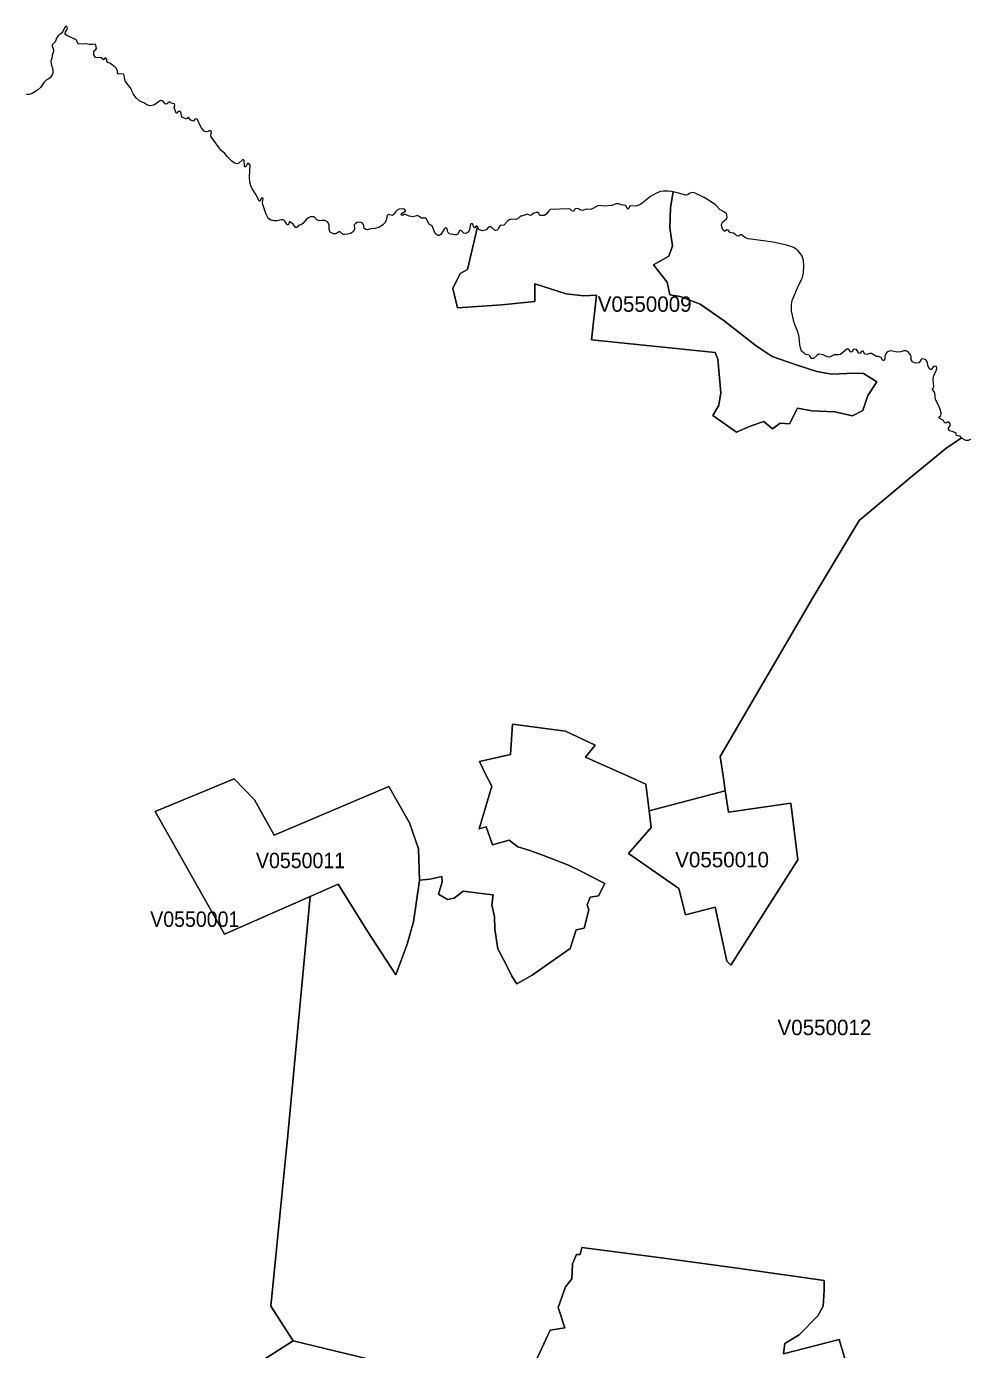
# Model space of a CAD drawing. Extents: x 369010 to 735936, y 6377141 to 6616555.
# Drawn here: x 434376 to 440462, y 6490450 to 6499050 of the extents above; entities that cross this region are included whole.
import ezdxf
from ezdxf.enums import TextEntityAlignment as Align

# ---------------------------------------------------------------- set-up
doc = ezdxf.new("R2010")
doc.units = 0
doc.header["$LTSCALE"] = 40
doc.layers.add('3', color=7, linetype='Continuous', lineweight=13)
doc.layers.add('4', color=7, linetype='Continuous')

msp = doc.modelspace()

# ---------------------------------------------------------------- linework, layer by layer
at = {"layer": '3'}
for points in [[(435015.02, 6498705), (435011.21, 6498730.82), (435006.25, 6498739.42), (434985.06, 6498742.4), (434977.62, 6498739.09), (434968.51, 6498743.39), (434967.69, 6498759.12), (434960.9, 6498776.83), (434951.47, 6498786.92), (434918.37, 6498811.09), (434906.12, 6498816.88), (434900, 6498823.66), (434898.01, 6498834.92), (434892.55, 6498844.85), (434887.09, 6498846.17), (434881.62, 6498836.57), (434877.32, 6498833.26), (434858.95, 6498849.48), (434839.59, 6498847.17), (434825.52, 6498848.82), (434820.06, 6498853.95), (434815.42, 6498866.86), (434814.43, 6498885.23), (434820.22, 6498896.82), (434826.68, 6498900.62), (434832.3, 6498907.41), (434827.67, 6498928.43), (434822.21, 6498936.04), (434804.83, 6498932.23), (434785.47, 6498931.9), (434759.65, 6498938.03), (434714.63, 6498936.04), (434701.06, 6498958.72), (434691.96, 6498966.66), (434638.17, 6498990.99), (434627.91, 6499000.92), (434631.05, 6499016.31), (434639.16, 6499029.22), (434643.63, 6499042.13), (434639.82, 6499050.24), (434631.05, 6499048.92), (434624.6, 6499041.8), (434612.35, 6499018.3), (434604.57, 6499007.7), (434582.39, 6498990.33), (434574.95, 6498978.41), (434563.03, 6498950.94), (434544, 6498930.91), (434543.33, 6498923.63), (434552.44, 6498897.81), (434552.11, 6498890.69), (434542.67, 6498864.21), (434540.52, 6498844.85), (434534.73, 6498825.48), (434536.88, 6498806.29), (434547.31, 6498767.56), (434547.31, 6498748.19), (434544.66, 6498735.29), (434530.43, 6498716.09), (434517.85, 6498707.15), (434505.1, 6498701.36), (434488.72, 6498686.3), (434468.53, 6498653.69), (434448.83, 6498635.65), (434412.92, 6498615.46), (434393.39, 6498608.18), (434375.68, 6498608.18)], [(436210.95, 6497807.3), (436199.7, 6497799.19), (436174.21, 6497769.24), (436162.63, 6497761.79), (436146.74, 6497757.65), (436133.83, 6497742.76), (436125.55, 6497742.76), (436109.66, 6497764.27), (436088.48, 6497780.16), (436084.34, 6497779.5), (436080.04, 6497761.79), (436074.25, 6497760.8), (436068.45, 6497765.27), (436057.2, 6497784.3), (436047.27, 6497792.41), (436031.71, 6497793.4), (436005.23, 6497786.95), (435984.71, 6497787.61), (435963.36, 6497793.4), (435953.1, 6497799.53), (435945.32, 6497808.79), (435932.74, 6497834.61), (435912.38, 6497892.7), (435911.23, 6497906.77), (435914.7, 6497933.25), (435908.91, 6497935.57), (435905.43, 6497934.58), (435894.34, 6497915.21), (435889.54, 6497915.54), (435869.52, 6497955.26), (435843.2, 6497993.83), (435834.1, 6498013.19), (435828.64, 6498039.01), (435825.99, 6498071.95), (435829.96, 6498147.58), (435822.85, 6498160.16), (435814.07, 6498158.67), (435803.15, 6498138.64), (435798.02, 6498137.32), (435792.89, 6498143.44), (435790.9, 6498179.85), (435787.43, 6498183.49), (435780.64, 6498183.99), (435757.47, 6498162.48), (435747.05, 6498156.68), (435729.01, 6498161.81), (435710.97, 6498175.05), (435682, 6498204.02), (435666.11, 6498223.71), (435640.96, 6498245.89), (435576.91, 6498333.61), (435575.25, 6498350.32), (435578.73, 6498359.76), (435576.58, 6498372), (435563.67, 6498372), (435554.9, 6498366.87), (435544.96, 6498365.22), (435531.39, 6498370.02), (435513.68, 6498391.04), (435498.29, 6498419.34), (435488.2, 6498446.15), (435484.39, 6498449.29), (435471.81, 6498448.47), (435463.04, 6498434.23), (435444.01, 6498441.02), (435429.94, 6498459.39), (435425.97, 6498459.39), (435419.18, 6498450.29), (435415.38, 6498449.96), (435391.54, 6498458.73), (435383.43, 6498467.67), (435382.44, 6498485.21), (435378.3, 6498494.48), (435371.19, 6498499.94), (435362.25, 6498496.79), (435353.15, 6498486.04), (435348.68, 6498486.04), (435337.42, 6498522.61), (435340.24, 6498538.67), (435338.25, 6498546.78), (435318.06, 6498550.91), (435310.28, 6498559.02), (435305.81, 6498560.18), (435296.05, 6498551.24), (435285.12, 6498546.11), (435278.67, 6498548.27), (435267.08, 6498560.84), (435259.31, 6498565.81), (435248.05, 6498567.96), (435203.86, 6498539), (435180.03, 6498534.2), (435158.84, 6498540.65), (435140.14, 6498554.39), (435114.32, 6498565.15), (435090.16, 6498586.33), (435069.47, 6498612.15), (435063.02, 6498624.4), (435057.89, 6498645.09), (435021.14, 6498692.09), (435015.02, 6498705)], [(437307.91, 6497746.73), (437244.36, 6497469.68), (437195.87, 6497444.52), (437148.7, 6497347.53), (437178.65, 6497220.43), (437465.8, 6497241.12), (437682.12, 6497261.64), (437681.46, 6497377.32), (437886.02, 6497311.95), (437999.72, 6497298.55), (438081.98, 6497304.17), (438049.87, 6497012.89), (438852.89, 6496929.8), (438870.93, 6496887.76), (438890.13, 6496669.13), (438877.72, 6496589.03), (438837.5, 6496520.35), (438992.91, 6496413.26), (439080.79, 6496452.16), (439169.67, 6496481.45), (439226.6, 6496434.95), (439276.75, 6496472.18), (439336.17, 6496467.05), (439388.13, 6496569.83), (439481.31, 6496552.29), (439631.76, 6496544.34), (439746.78, 6496519.35), (439812.82, 6496554.27), (439846.58, 6496652.42), (439904.84, 6496740.3), (439818.61, 6496794.25), (439759.69, 6496796.74), (439609.91, 6496790.12), (439515.57, 6496806.34), (439386.15, 6496847.71), (439224.95, 6496904.81), (439119.52, 6496973.99), (438912.31, 6497137.18), (438755.91, 6497244.59), (438626.48, 6497295.23), (438558.63, 6497306.16), (438542.41, 6497388.25), (438453.04, 6497499.8), (438551.84, 6497556.57), (438577, 6497624.92), (438558.3, 6497741.93), (438562.93, 6497872.51), (438580.64, 6497974.3), (438580.64, 6497974.63), (438569.39, 6497977.11), (438546.05, 6497980.09), (438517.09, 6497980.59), (438496.4, 6497976.45), (438463.63, 6497962.55), (438433.84, 6497945.17), (438367.47, 6497892.04), (438338.51, 6497881.45), (438301.43, 6497884.59), (438297.13, 6497880.95), (438292.99, 6497868.04), (438286.04, 6497862.75), (438281.57, 6497865.89), (438272.31, 6497886.42), (438242.51, 6497891.38), (438226.3, 6497898.17), (438210.9, 6497897.84), (438179.95, 6497885.92), (438133.45, 6497882.94), (438094.72, 6497885.59), (438046.39, 6497860.1), (438015.44, 6497863.58), (437990.29, 6497854.64), (437979.36, 6497856.62), (437960, 6497865.89), (437945.93, 6497865.56), (437940.8, 6497863.08), (437931.7, 6497847.85), (437922.26, 6497851.66), (437911.01, 6497863.24), (437900.75, 6497865.23), (437780.76, 6497859.44), (437771.49, 6497851), (437755.6, 6497829.81), (437743.35, 6497821.37), (437716.71, 6497821.37), (437711.58, 6497825.68), (437707.61, 6497835.61), (437700.82, 6497841.07), (437689.9, 6497841.73), (437674.84, 6497837.26), (437654.48, 6497821.7), (437646.04, 6497822.7), (437634.45, 6497830.14), (437594.57, 6497817.23), (437587.45, 6497817.57), (437572.55, 6497802.67), (437558.32, 6497795.88), (437532.67, 6497796.55), (437517.11, 6497793.4), (437503.54, 6497784.63)], [(439435.8, 6496922.69), (439415.44, 6496939.07), (439408.32, 6496960.42), (439404.52, 6496981.6), (439400.71, 6497031.26), (439392.6, 6497059.72), (439367.11, 6497123.44), (439350.4, 6497201.56), (439350.4, 6497242.11), (439353.21, 6497267.93), (439389.13, 6497351.67), (439415.44, 6497405.3), (439420.57, 6497419.36), (439427.03, 6497448.49), (439430.01, 6497493.51), (439427.36, 6497528.43), (439418.42, 6497557.39), (439410.97, 6497570.63), (439392.27, 6497592.48), (439370.76, 6497609.86), (439359, 6497616.15), (439318.46, 6497628.39), (439231.4, 6497647.1), (439167.68, 6497657.69), (439069.04, 6497669.61), (439045.71, 6497678.54), (439031.64, 6497691.45), (439023.86, 6497695.09), (439018.73, 6497695.09), (439004.5, 6497687.98), (438994.23, 6497689.3), (438972.22, 6497707.34), (438956.83, 6497708.66), (438950.71, 6497711.48), (438939.12, 6497727.03), (438930.35, 6497727.86), (438919.43, 6497719.92), (438914.3, 6497719.59), (438904.2, 6497728.52), (438896.42, 6497748.22), (438895.59, 6497759.8), (438900.39, 6497778.18), (438927.37, 6497799.19), (438931.34, 6497808.79), (438930.35, 6497826.17), (438924.89, 6497835.27), (438914.3, 6497844.05), (438886.16, 6497858.45), (438855.21, 6497889.73), (438821.78, 6497915.21), (438782.72, 6497938.38), (438724.63, 6497965.53), (438707.25, 6497970.33), (438692.19, 6497967.18), (438673.82, 6497956.09), (438662.07, 6497954.27), (438615.73, 6497967.18), (438580.64, 6497974.63), (438580.64, 6497974.3), (438562.93, 6497872.51), (438558.3, 6497741.93), (438577, 6497624.92), (438551.84, 6497556.57), (438453.04, 6497499.8), (438542.41, 6497388.25), (438558.63, 6497306.16), (438626.48, 6497295.23), (438755.91, 6497244.59), (438912.31, 6497137.18), (439119.52, 6496973.99), (439224.95, 6496904.81), (439386.15, 6496847.71), (439515.57, 6496806.34), (439609.91, 6496790.12), (439759.69, 6496796.74), (439818.61, 6496794.25), (439904.84, 6496740.3), (439846.58, 6496652.42), (439812.82, 6496554.27), (439746.78, 6496519.35), (439631.76, 6496544.34), (439481.31, 6496552.29), (439388.13, 6496569.83), (439336.17, 6496467.05), (439276.75, 6496472.18), (439226.6, 6496434.95), (439169.67, 6496481.45), (439080.79, 6496452.16), (438992.91, 6496413.26), (438837.5, 6496520.35), (438877.72, 6496589.03), (438890.13, 6496669.13), (438870.93, 6496887.76), (438852.89, 6496929.8), (438049.87, 6497012.89), (438081.98, 6497304.17), (437999.72, 6497298.55), (437886.02, 6497311.95), (437681.46, 6497377.32), (437682.12, 6497261.64)], [(437682.12, 6497261.64), (437465.8, 6497241.12), (437178.65, 6497220.43), (437148.7, 6497347.53), (437195.87, 6497444.52), (437244.36, 6497469.68), (437307.91, 6497746.73), (437305.27, 6497751.2), (437299.64, 6497753.18), (437291.36, 6497741.27), (437288.05, 6497741.93), (437276.96, 6497768.25), (437264.39, 6497766.59), (437260.58, 6497756.66), (437256.61, 6497728.19), (437248.66, 6497713.13), (437232.44, 6497705.35), (437220.53, 6497707.34), (437205.14, 6497722.07), (437196.03, 6497725.38), (437189.25, 6497720.25), (437181.63, 6497699.89), (437174.19, 6497695.42), (437159.95, 6497695.75), (437127.35, 6497702.71), (437114.77, 6497712.8), (437111.96, 6497735.64), (437105.5, 6497741.1), (437101.36, 6497741.1), (437092.59, 6497732.17), (437069.42, 6497696.91), (437059.66, 6497690.46), (437049.73, 6497691.78), (437036.82, 6497699.89), (437026.23, 6497718.59), (437016.79, 6497750.54), (437011, 6497756.33), (436998.09, 6497761.46), (436991.64, 6497767.58), (436977.9, 6497799.19), (436971.11, 6497803.33), (436944.63, 6497803.99), (436918.15, 6497821.7), (436890.51, 6497811.77), (436864.69, 6497816.9), (436840.53, 6497828.49), (436831.1, 6497828.49), (436821.5, 6497822.03), (436811.9, 6497825.01), (436813.72, 6497834.61), (436839.54, 6497850.17), (436840.86, 6497854.31), (436835.07, 6497863.24), (436821.5, 6497864.9), (436800.15, 6497862.09), (436787.24, 6497855.96), (436774.49, 6497844.38), (436763.41, 6497827.5), (436755.46, 6497821.37), (436728.32, 6497827.5), (436720.87, 6497820.38), (436714.42, 6497789.43), (436706.47, 6497773.38), (436693.56, 6497759.8), (436671.88, 6497745.9), (436643.58, 6497737.63), (436615.11, 6497735.64), (436590.95, 6497728.86), (436583.67, 6497729.85), (436571.75, 6497736.3), (436569.43, 6497755.01), (436565.79, 6497765.6), (436558.18, 6497773.04), (436540.97, 6497777.51), (436526.9, 6497775.03), (436515.31, 6497768.91), (436506.54, 6497759.8), (436508.53, 6497732.5), (436502.74, 6497716.61), (436483.7, 6497705.35), (436464.34, 6497699.89), (436444.98, 6497697.58), (436435.71, 6497698.57), (436416.01, 6497714.79), (436408.56, 6497715.95), (436386.88, 6497702.54), (436371.49, 6497703.04), (436351.13, 6497713.13), (436347.66, 6497717.27), (436344.35, 6497732.83), (436345.34, 6497758.48), (436340.21, 6497771.39), (436333.43, 6497780.16), (436317.37, 6497788.27), (436298.01, 6497788.6), (436278.64, 6497785.95), (436263.42, 6497793.73), (436246.04, 6497812.43), (436223.86, 6497811.77), (436210.95, 6497807.3)], [(437503.54, 6497784.63), (437479.71, 6497758.81), (437456.54, 6497755.34), (437450.41, 6497748.22), (437443.63, 6497732.17), (437436.51, 6497726.7), (437424.59, 6497724.06), (437419.79, 6497726.04), (437398.11, 6497747.23), (437385.87, 6497747.23), (437380.74, 6497745.07), (437365.01, 6497729.19), (437349.46, 6497723.06), (437341.18, 6497722.73), (437320.82, 6497727.86), (437317.02, 6497730.84), (437307.91, 6497746.73)], [(440412.6, 6496410.78), (440394.56, 6496418.23), (440379.67, 6496421.04), (440373.88, 6496425.01), (440370.07, 6496432.46), (440369.74, 6496440.08), (440381.65, 6496455.63), (440382.32, 6496468.21), (440372.55, 6496477.15), (440362.29, 6496477.15), (440358.32, 6496474.67), (440347.73, 6496473.01), (440344.25, 6496475.49), (440337.46, 6496488.4), (440313.63, 6496502.31), (440310.65, 6496507.1), (440310.65, 6496512.9), (440320.09, 6496522.33), (440323.23, 6496529.12), (440323.23, 6496538.05), (440317.44, 6496559.4), (440305.52, 6496589.36), (440285.83, 6496625.77), (440282.68, 6496669.3), (440265.8, 6496689.66), (440266.13, 6496693.79), (440272.92, 6496702.23), (440275.23, 6496710.84), (440270.77, 6496753.37), (440272.92, 6496774.72), (440291.95, 6496817.26), (440294.27, 6496828.84), (440291.62, 6496839.27), (440288.48, 6496841.42), (440273.91, 6496839.44), (440258.85, 6496820.24), (440253.88, 6496819.91), (440246.27, 6496824.05), (440239.15, 6496840.43), (440231.38, 6496871.38), (440221.45, 6496885.61), (440210.69, 6496888.59), (440197.78, 6496888.76), (440192.32, 6496885.94), (440185.86, 6496873.7), (440177.26, 6496863.1), (440156.9, 6496862.11), (440136.54, 6496870.22), (440127.27, 6496882.14), (440128.27, 6496905.64), (440125.62, 6496912.76), (440111.39, 6496931.46), (440100.46, 6496940.39), (440092.85, 6496942.38), (440079.94, 6496941.72), (440060.58, 6496935.93), (440034.1, 6496933.94), (439998.68, 6496940.73), (439985.77, 6496940.06), (439969.88, 6496932.28), (439968.72, 6496929.14), (439964.75, 6496927.49), (439957.63, 6496906.3), (439956.81, 6496890.74), (439951.51, 6496879.82), (439944.23, 6496879.16), (439931.98, 6496898.19), (439915.43, 6496904.31), (439902.52, 6496905.64), (439870.58, 6496923.35), (439859.99, 6496924.67), (439839.96, 6496918.88), (439827.22, 6496920.7), (439815.3, 6496938.74), (439810.67, 6496939.07), (439805.2, 6496936.59), (439794.28, 6496925), (439787.16, 6496925.5), (439772.6, 6496949.5), (439756.88, 6496951.98), (439750.42, 6496948.17), (439741.98, 6496933.94), (439732.71, 6496934.27), (439724.93, 6496949.17), (439719.47, 6496952.31), (439710.37, 6496951.65), (439668.17, 6496917.55), (439655.59, 6496915.57), (439627.95, 6496915.57), (439596.01, 6496900.84), (439580.78, 6496903.65), (439555.13, 6496915.24), (439527.98, 6496919.54), (439515.74, 6496913.91), (439492.24, 6496892.07), (439480.65, 6496891.74), (439469.73, 6496908.78), (439464.1, 6496913.09), (439444.9, 6496917.89), (439435.8, 6496922.69)], [(440645.3, 6496319.59), (440640.83, 6496323.06), (440630.74, 6496349.21), (440622.13, 6496351.86), (440595.65, 6496352.69), (440586.22, 6496360.14), (440587.87, 6496372.38), (440649.11, 6496528.45), (440653.41, 6496531.27), (440653.91, 6496534.91), (440649.77, 6496536.56), (440641.66, 6496533.25), (440581.09, 6496378.84), (440574.3, 6496373.05), (440556.26, 6496365.6), (440546.66, 6496365.93), (440532.43, 6496370.23), (440518.36, 6496367.25), (440498.33, 6496358.48), (440484.1, 6496359.14), (440460.1, 6496372.22), (440455.14, 6496377.18)], [(435519.31, 6490129.24), (436110.33, 6490505.93), (436109.66, 6490506.92), (435965.84, 6490731.51), (436074.91, 6491842.21), (436221.21, 6493395.3), (435664.13, 6493149.86), (435212.8, 6493947.25), (435726.69, 6494158.6), (435859.59, 6494023.39), (435986.03, 6493793.67), (436732.13, 6494110.11), (436865.69, 6493873.11), (436925.76, 6493704.46), (436930.56, 6493501.06), (436997.92, 6493507.68), (437077.2, 6493523.9), (437078.36, 6493489.64), (437054.53, 6493410.36), (437113.94, 6493376.1), (437157.64, 6493383.71), (437215.73, 6493430.05), (437368.49, 6493410.03), (437410.36, 6493405.39), (437402.75, 6493340.35), (437418.3, 6493263.56), (437422.28, 6493183.29), (437440.98, 6493054.36), (437496.59, 6492948.77), (437532.01, 6492876.61), (437563.62, 6492826.96), (437664.57, 6492883.39), (437911.34, 6493055.85), (437950.73, 6493177.83), (438001.21, 6493188.25), (438032.82, 6493306.92), (438022.56, 6493340.35), (438040.6, 6493389.67), (438096.21, 6493398.77), (438136.76, 6493478.71), (437970.76, 6493562.79), (437899.92, 6493597.38), (437727.14, 6493666.39), (437643.39, 6493696.68), (437571.06, 6493717.04), (437513.97, 6493761.56), (437405.56, 6493730.44), (437364.35, 6493848.45), (437318.51, 6493834.22), (437401.75, 6494112.43), (437361.37, 6494190.71), (437322.64, 6494272.8), (437523.73, 6494316.83), (437537.14, 6494514.77), (437881.22, 6494469.92), (438072.87, 6494378.89), (438011.14, 6494299.61), (438287.37, 6494176.15), (438403.55, 6494124.51), (438423.74, 6493952.39), (438918.93, 6494082.31), (438907.34, 6494164.73), (438886.66, 6494305.74), (439491.24, 6495340.8), (439788.82, 6495839.79), (440123.3, 6496118.01), (440352.53, 6496306.35), (440454.48, 6496376.69), (440455.14, 6496377.18), (440448.68, 6496383.31), (440441.57, 6496387.28), (440422.2, 6496391.09), (440419.39, 6496403.66), (440412.6, 6496410.78)], [(440455.14, 6496377.18), (440454.48, 6496376.69), (440352.53, 6496306.35), (440123.3, 6496118.01), (439788.82, 6495839.79), (439491.24, 6495340.8), (438886.66, 6494305.74), (438907.34, 6494164.73), (438918.93, 6494082.31), (438940.44, 6493942.45), (439345.93, 6494001.71), (439391.61, 6493633.29), (438954.51, 6492948.6), (438930.02, 6492973.76), (438854.22, 6493326.28), (438659.75, 6493275.47), (438617.22, 6493445.78), (438290.84, 6493673.18), (438437.48, 6493842.33), (438423.74, 6493952.39), (438403.55, 6494124.51), (438287.37, 6494176.15), (438011.14, 6494299.61), (438072.87, 6494378.89), (437881.22, 6494469.92), (437537.14, 6494514.77), (437523.73, 6494316.83), (437322.64, 6494272.8), (437361.37, 6494190.71), (437401.75, 6494112.43), (437318.51, 6493834.22), (437364.35, 6493848.45), (437405.56, 6493730.44), (437513.97, 6493761.56), (437571.06, 6493717.04), (437643.39, 6493696.68), (437727.14, 6493666.39), (437899.92, 6493597.38), (437970.76, 6493562.79), (438136.76, 6493478.71), (438096.21, 6493398.77), (438040.6, 6493389.67), (438022.56, 6493340.35), (438032.82, 6493306.92), (438001.21, 6493188.25), (437950.73, 6493177.83), (437911.34, 6493055.85), (437664.57, 6492883.39), (437563.62, 6492826.96), (437532.01, 6492876.61), (437496.59, 6492948.77), (437440.98, 6493054.36), (437422.28, 6493183.29), (437418.3, 6493263.56), (437402.75, 6493340.35), (437410.36, 6493405.39), (437368.49, 6493410.03), (437215.73, 6493430.05), (437157.64, 6493383.71), (437113.94, 6493376.1), (437054.53, 6493410.36), (437078.36, 6493489.64), (437077.2, 6493523.9), (436997.92, 6493507.68), (436930.56, 6493501.06), (436930.56, 6493499.07), (436892.33, 6493230.79), (436852.28, 6493085.81), (436778.14, 6492886.54), (436596.41, 6493164.26), (436402.11, 6493475.07), (436221.21, 6493395.3), (436074.91, 6491842.21), (435965.84, 6490731.51), (436109.66, 6490506.92), (436110.33, 6490505.93), (437631.14, 6490138.84)], [(440006.29, 6489352.37), (439660.88, 6490514.87), (439298.43, 6490421.36), (439305.55, 6490489.05), (439399.72, 6490545.15), (439521.7, 6490669.78), (439555.95, 6490731.02), (439561.91, 6490836.61), (439563.24, 6490898.51), (439028.99, 6490973.98), (438520.23, 6491043.98), (437987.97, 6491112.5), (437975.06, 6491066.66), (437952.39, 6491067.32), (437925.24, 6491007.9), (437922.1, 6490909.1), (437880.72, 6490858.29), (437833.55, 6490722.57), (437876.09, 6490591.5), (437780.59, 6490576.1), (437671.19, 6490336.45)], [(437671.19, 6490336.45), (437780.59, 6490576.1), (437876.09, 6490591.5), (437833.55, 6490722.57), (437880.72, 6490858.29), (437922.1, 6490909.1), (437925.24, 6491007.9), (437952.39, 6491067.32), (437975.06, 6491066.66), (437987.97, 6491112.5), (438520.23, 6491043.98), (439028.99, 6490973.98), (439563.24, 6490898.51), (439561.91, 6490836.61), (439555.95, 6490731.02), (439521.7, 6490669.78), (439399.72, 6490545.15), (439305.55, 6490489.05), (439298.43, 6490421.36), (439660.88, 6490514.87), (440006.29, 6489352.37)], [(437631.14, 6490138.84), (436110.33, 6490505.93), (435519.31, 6490129.24)]]:
    msp.add_lwpolyline(points, dxfattribs=at)
for points in [[(436221.21, 6493395.3), (436402.11, 6493475.07), (436596.41, 6493164.26), (436778.14, 6492886.54), (436852.28, 6493085.81), (436892.33, 6493230.79), (436930.56, 6493499.07), (436930.56, 6493501.06), (436925.76, 6493704.46), (436865.69, 6493873.11), (436732.13, 6494110.11), (435986.03, 6493793.67), (435859.59, 6494023.39), (435726.69, 6494158.6), (435212.8, 6493947.25), (435664.13, 6493149.86)], [(438918.93, 6494082.31), (438423.74, 6493952.39), (438437.48, 6493842.33), (438290.84, 6493673.18), (438617.22, 6493445.78), (438659.75, 6493275.47), (438854.22, 6493326.28), (438930.02, 6492973.76), (438954.51, 6492948.6), (439391.61, 6493633.29), (439345.93, 6494001.71), (438940.44, 6493942.45)]]:
    msp.add_lwpolyline(points, close=True, dxfattribs=at)

# ---------------------------------------------------------------- texts
at = {"layer": '4'}
for s, p in [('V0550009', (438395.48, 6497195.55)), ('V0550010', (438898.68, 6493584.35)), ('V0550012', (439563.88, 6492493.35))]:
    msp.add_text(s, height=100, dxfattribs=at).set_placement(p, align=Align.CENTER)
at = {"layer": '4', "width": 0.95}
for s, p in [('V0550011', (436158.24, 6493578.83)), ('V0550001', (435470.68, 6493197.36))]:
    msp.add_text(s, height=100, dxfattribs=at).set_placement(p, align=Align.CENTER)

doc.saveas('drawing.dxf')
